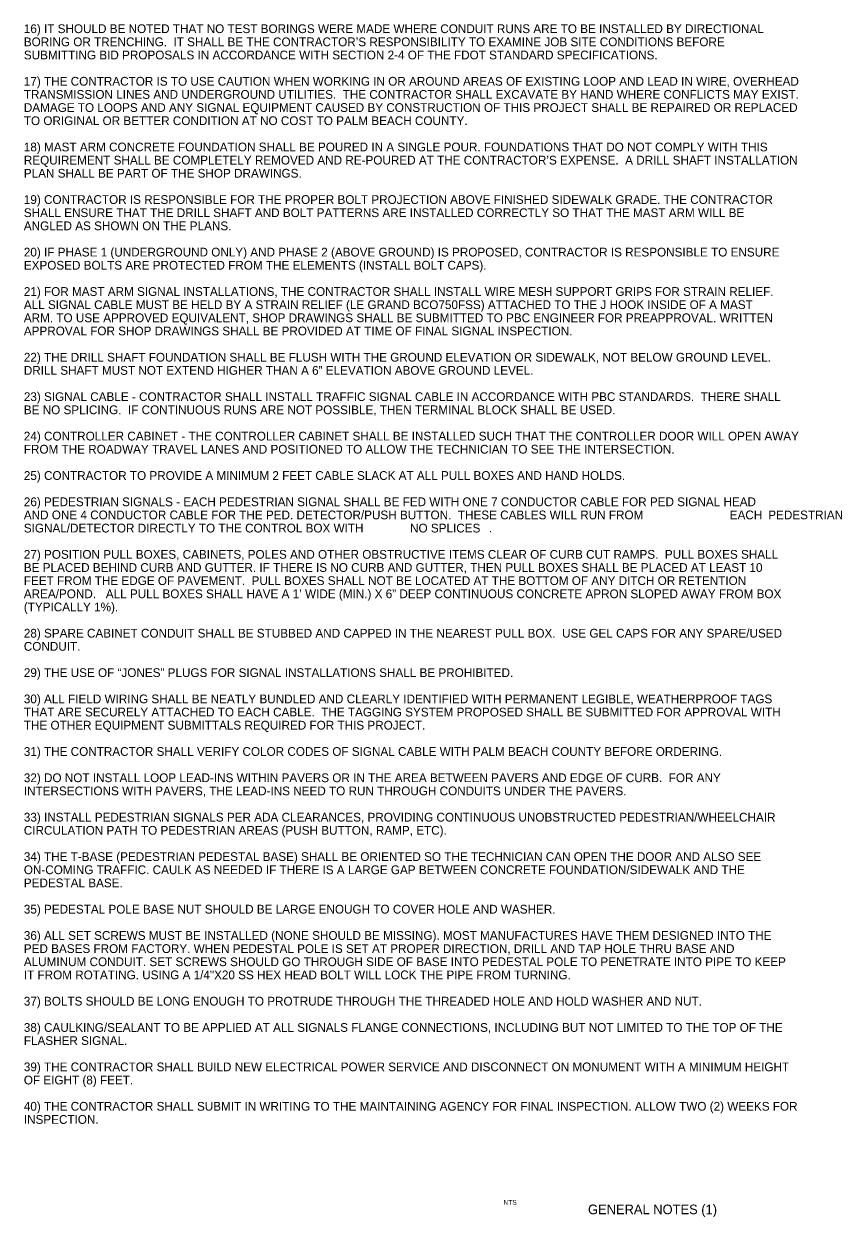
# Model space of a CAD drawing. Extents: x -1.6 to 33.4, y -12.7 to 10.9.
# Drawn here: x 25.84 to 32.38, y -0.23 to 9.31 of the extents above; entities that cross this region are included whole.
import ezdxf

# ---------------------------------------------------------------- set-up
doc = ezdxf.new("R2010")
doc.units = 0
doc.layers.add('NonPlottingEle_dp', color=7, linetype='Continuous')

msp = doc.modelspace()

# ---------------------------------------------------------------- texts
at = {"layer": 'NonPlottingEle_dp'}
for s, height, p in [('16) IT SHOULD BE NOTED THAT NO TEST BORINGS WERE MADE WHERE CONDUIT RUNS ARE TO BE INSTALLED BY DIRECTIONAL ', 0.07, (25.841, 9.2341)), ('BORING OR TRENCHING.  IT SHALL BE THE CONTRACTOR’S RESPONSIBILITY TO EXAMINE JOB SITE CONDITIONS BEFORE ', 0.07, (25.841, 9.1291)), ('SUBMITTING BID PROPOSALS IN ACCORDANCE WITH SECTION 2-4 OF THE FDOT STANDARD SPECIFICATIONS.   ', 0.07, (25.841, 9.0241)), ('17) THE CONTRACTOR IS TO USE CAUTION WHEN WORKING IN OR AROUND AREAS OF EXISTING LOOP AND LEAD IN WIRE, OVERHEAD ', 0.07, (25.841, 8.8141)), ('TRANSMISSION LINES AND UNDERGROUND UTILITIES.  THE CONTRACTOR SHALL EXCAVATE BY HAND WHERE CONFLICTS MAY EXIST.  ', 0.07, (25.841, 8.7091)), ('DAMAGE TO LOOPS AND ANY SIGNAL EQUIPMENT CAUSED BY CONSTRUCTION OF THIS PROJECT SHALL BE REPAIRED OR REPLACED ', 0.07, (25.841, 8.6041)), ('TO ORIGINAL OR BETTER CONDITION AT NO COST TO PALM BEACH COUNTY.', 0.07, (25.841, 8.4991)), ('18) MAST ARM CONCRETE FOUNDATION SHALL BE POURED IN A SINGLE POUR. FOUNDATIONS THAT DO NOT COMPLY WITH THIS ', 0.07, (25.841, 8.2891)), ('REQUIREMENT SHALL BE COMPLETELY REMOVED AND RE-POURED AT THE CONTRACTOR’S EXPENSE.  A DRILL SHAFT INSTALLATION ', 0.07, (25.841, 8.1841)), ('PLAN SHALL BE PART OF THE SHOP DRAWINGS. ', 0.07, (25.841, 8.0791)), ('19) CONTRACTOR IS RESPONSIBLE FOR THE PROPER BOLT PROJECTION ABOVE FINISHED SIDEWALK GRADE. THE CONTRACTOR ', 0.07, (25.841, 7.8691)), ('SHALL ENSURE THAT THE DRILL SHAFT AND BOLT PATTERNS ARE INSTALLED CORRECTLY SO THAT THE MAST ARM WILL BE ', 0.07, (25.841, 7.7641)), ('ANGLED AS SHOWN ON THE PLANS.  ', 0.07, (25.841, 7.6591)), ('20) IF PHASE 1 (UNDERGROUND ONLY) AND PHASE 2 (ABOVE GROUND) IS PROPOSED, CONTRACTOR IS RESPONSIBLE TO ENSURE ', 0.07, (25.841, 7.4491)), ('EXPOSED BOLTS ARE PROTECTED FROM THE ELEMENTS (INSTALL BOLT CAPS).   ', 0.07, (25.841, 7.3441)), ('21) FOR MAST ARM SIGNAL INSTALLATIONS, THE CONTRACTOR SHALL INSTALL WIRE MESH SUPPORT GRIPS FOR STRAIN RELIEF. ', 0.07, (25.841, 7.1341)), ('ALL SIGNAL CABLE MUST BE HELD BY A STRAIN RELIEF (LE GRAND BCO750FSS) ATTACHED TO THE J HOOK INSIDE OF A MAST ', 0.07, (25.841, 7.0291)), ('ARM. TO USE APPROVED EQUIVALENT, SHOP DRAWINGS SHALL BE SUBMITTED TO PBC ENGINEER FOR PREAPPROVAL. WRITTEN ', 0.07, (25.841, 6.9241)), ('APPROVAL FOR SHOP DRAWINGS SHALL BE PROVIDED AT TIME OF FINAL SIGNAL INSPECTION.   ', 0.07, (25.841, 6.8191)), ('22) THE DRILL SHAFT FOUNDATION SHALL BE FLUSH WITH THE GROUND ELEVATION OR SIDEWALK, NOT BELOW GROUND LEVEL.  ', 0.07, (25.841, 6.6091)), ('DRILL SHAFT MUST NOT EXTEND HIGHER THAN A 6” ELEVATION ABOVE GROUND LEVEL.', 0.07, (25.841, 6.5041)), ('23) SIGNAL CABLE - CONTRACTOR SHALL INSTALL TRAFFIC SIGNAL CABLE IN ACCORDANCE WITH PBC STANDARDS.  THERE SHALL ', 0.07, (25.841, 6.2941)), ('BE NO SPLICING.  IF CONTINUOUS RUNS ARE NOT POSSIBLE, THEN TERMINAL BLOCK SHALL BE USED.', 0.07, (25.841, 6.1891)), ('24) CONTROLLER CABINET - THE CONTROLLER CABINET SHALL BE INSTALLED SUCH THAT THE CONTROLLER DOOR WILL OPEN AWAY ', 0.07, (25.841, 5.9791)), ('FROM THE ROADWAY TRAVEL LANES AND POSITIONED TO ALLOW THE TECHNICIAN TO SEE THE INTERSECTION.   ', 0.07, (25.841, 5.8741)), ('25) CONTRACTOR TO PROVIDE A MINIMUM 2 FEET CABLE SLACK AT ALL PULL BOXES AND HAND HOLDS. ', 0.07, (25.841, 5.6641)), ('26) PEDESTRIAN SIGNALS - EACH PEDESTRIAN SIGNAL SHALL BE FED WITH ONE 7 CONDUCTOR CABLE FOR PED SIGNAL HEAD ', 0.07, (25.841, 5.4541)), ('AND ONE 4 CONDUCTOR CABLE FOR THE PED. DETECTOR/PUSH BUTTON.  THESE CABLES WILL RUN FROM ', 0.07, (25.841, 5.3491)), ('EACH', 0.07, (31.4828, 5.3491)), (' PEDESTRIAN ', 0.07, (31.7646, 5.3491)), ('SIGNAL/DETECTOR DIRECTLY TO THE CONTROL BOX WITH ', 0.07, (25.841, 5.2441)), ('NO SPLICES', 0.07, (28.9278, 5.2441)), ('.  ', 0.07, (29.558, 5.2441)), ('27) POSITION PULL BOXES, CABINETS, POLES AND OTHER OBSTRUCTIVE ITEMS CLEAR OF CURB CUT RAMPS.  PULL BOXES SHALL ', 0.07, (25.841, 5.0341)), ('BE PLACED BEHIND CURB AND GUTTER. IF THERE IS NO CURB AND GUTTER, THEN PULL BOXES SHALL BE PLACED AT LEAST 10 ', 0.07, (25.841, 4.9291)), ('FEET FROM THE EDGE OF PAVEMENT.  PULL BOXES SHALL NOT BE LOCATED AT THE BOTTOM OF ANY DITCH OR RETENTION ', 0.07, (25.841, 4.8241)), ('AREA/POND.   ALL PULL BOXES SHALL HAVE A 1’ WIDE (MIN.) X 6” DEEP CONTINUOUS CONCRETE APRON SLOPED AWAY FROM BOX ', 0.07, (25.841, 4.7191)), ('(TYPICALLY 1%). ', 0.07, (25.841, 4.6141)), ('28) SPARE CABINET CONDUIT SHALL BE STUBBED AND CAPPED IN THE NEAREST PULL BOX.  USE GEL CAPS FOR ANY SPARE/USED ', 0.07, (25.841, 4.4041)), ('CONDUIT. ', 0.07, (25.841, 4.2991)), ('29) THE USE OF “JONES” PLUGS FOR SIGNAL INSTALLATIONS SHALL BE PROHIBITED.', 0.07, (25.841, 4.0891)), ('30) ALL FIELD WIRING SHALL BE NEATLY BUNDLED AND CLEARLY IDENTIFIED WITH PERMANENT LEGIBLE, WEATHERPROOF TAGS ', 0.07, (25.841, 3.8791)), ('THAT ARE SECURELY ATTACHED TO EACH CABLE.  THE TAGGING SYSTEM PROPOSED SHALL BE SUBMITTED FOR APPROVAL WITH ', 0.07, (25.841, 3.7741)), ('THE OTHER EQUIPMENT SUBMITTALS REQUIRED FOR THIS PROJECT.', 0.07, (25.841, 3.6691)), ('31) THE CONTRACTOR SHALL VERIFY COLOR CODES OF SIGNAL CABLE WITH PALM BEACH COUNTY BEFORE ORDERING. ', 0.07, (25.841, 3.4591)), ('32) DO NOT INSTALL LOOP LEAD-INS WITHIN PAVERS OR IN THE AREA BETWEEN PAVERS AND EDGE OF CURB.  FOR ANY ', 0.07, (25.841, 3.2491)), ('INTERSECTIONS WITH PAVERS, THE LEAD-INS NEED TO RUN THROUGH CONDUITS UNDER THE PAVERS. ', 0.07, (25.841, 3.1441)), ('33) INSTALL PEDESTRIAN SIGNALS PER ADA CLEARANCES, PROVIDING CONTINUOUS UNOBSTRUCTED PEDESTRIAN/WHEELCHAIR ', 0.07, (25.841, 2.9341)), ('CIRCULATION PATH TO PEDESTRIAN AREAS (PUSH BUTTON, RAMP, ETC).  ', 0.07, (25.841, 2.8291)), ('34) THE T-BASE (PEDESTRIAN PEDESTAL BASE) SHALL BE ORIENTED SO THE TECHNICIAN CAN OPEN THE DOOR AND ALSO SEE ', 0.07, (25.841, 2.6191)), ('ON-COMING TRAFFIC. CAULK AS NEEDED IF THERE IS A LARGE GAP BETWEEN CONCRETE FOUNDATION/SIDEWALK AND THE ', 0.07, (25.841, 2.5141)), ('PEDESTAL BASE. ', 0.07, (25.841, 2.4091)), ('35) PEDESTAL POLE BASE NUT SHOULD BE LARGE ENOUGH TO COVER HOLE AND WASHER.', 0.07, (25.841, 2.1991)), ('36) ALL SET SCREWS MUST BE INSTALLED (NONE SHOULD BE MISSING). MOST MANUFACTURES HAVE THEM DESIGNED INTO THE ', 0.07, (25.841, 1.9891)), ('PED BASES FROM FACTORY. WHEN PEDESTAL POLE IS SET AT PROPER DIRECTION, DRILL AND TAP HOLE THRU BASE AND ', 0.07, (25.841, 1.8841)), ('ALUMINUM CONDUIT. SET SCREWS SHOULD GO THROUGH SIDE OF BASE INTO PEDESTAL POLE TO PENETRATE INTO PIPE TO KEEP ', 0.07, (25.841, 1.7791)), ('IT FROM ROTATING. USING A 1/4"X20 SS HEX HEAD BOLT WILL LOCK THE PIPE FROM TURNING.', 0.07, (25.841, 1.6741)), ('37) BOLTS SHOULD BE LONG ENOUGH TO PROTRUDE THROUGH THE THREADED HOLE AND HOLD WASHER AND NUT.', 0.07, (25.841, 1.4641)), ('38) CAULKING/SEALANT TO BE APPLIED AT ALL SIGNALS FLANGE CONNECTIONS, INCLUDING BUT NOT LIMITED TO THE TOP OF THE ', 0.07, (25.841, 1.2541)), ('FLASHER SIGNAL.', 0.07, (25.841, 1.1491)), ('39) THE CONTRACTOR SHALL BUILD NEW ELECTRICAL POWER SERVICE AND DISCONNECT ON MONUMENT WITH A MINIMUM HEIGHT ', 0.07, (25.841, 0.9391)), ('OF EIGHT (8) FEET. ', 0.07, (25.841, 0.8341)), ('40) THE CONTRACTOR SHALL SUBMIT IN WRITING TO THE MAINTAINING AGENCY FOR FINAL INSPECTION. ALLOW TWO (2) WEEKS FOR ', 0.07, (25.841, 0.6241)), ('INSPECTION.', 0.07, (25.841, 0.5191)), ('NTS', 0.03855, (29.6745, -0.1278)), ('   GENERAL NOTES (1)    ', 0.077091, (30.2643, -0.2032))]:
    msp.add_text(s, height=height, dxfattribs=at).set_placement(p)

doc.saveas('drawing.dxf')
